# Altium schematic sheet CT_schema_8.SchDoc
size 278 x 170 mm
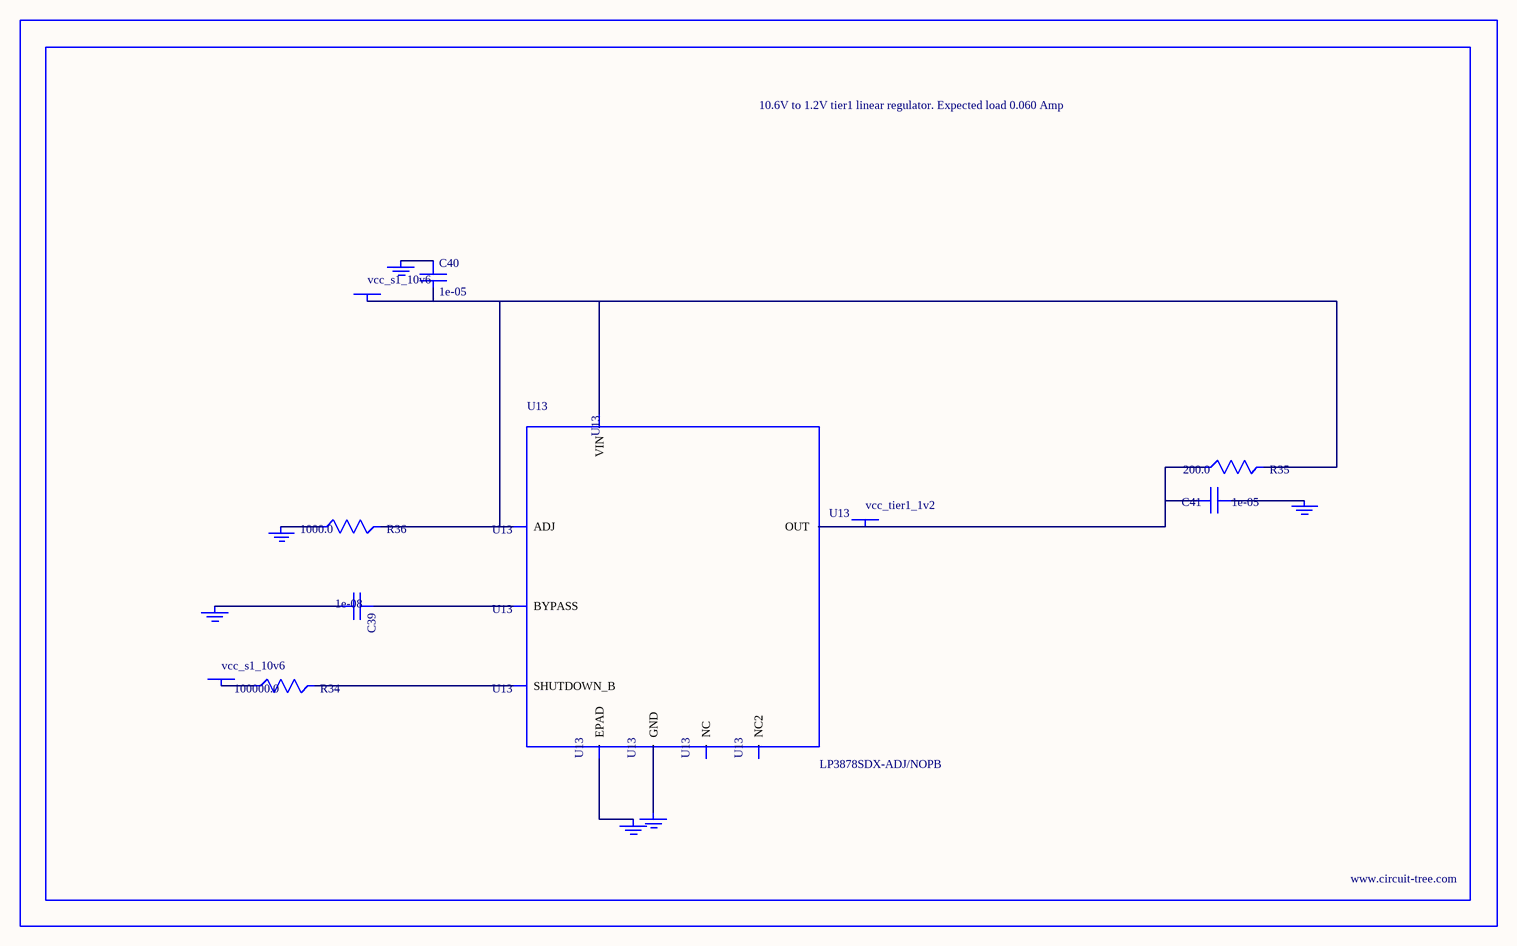
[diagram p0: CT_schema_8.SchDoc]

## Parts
BORDER7  (no value)
C39  1e-08  [C0402]
C40  1e-05  [C1206]
C41  1e-05  [C0805]
GND_INSTANCE_7_0  (no value)
GND_INSTANCE_7_1  (no value)
GND_INSTANCE_7_2  (no value)
GND_INSTANCE_7_3  (no value)
GND_INSTANCE_7_4  (no value)
GND_INSTANCE_7_5  (no value)
POWER_INSTANCE_7_0  vcc_s1_10v6
POWER_INSTANCE_7_1  vcc_s1_10v6
POWER_INSTANCE_7_2  vcc_tier1_1v2
R34  100000.0  [R0603]
R35  200.0  [R0603]
R36  1000.0  [R0603]
U13  LP3878SDX-ADJ/NOPB  [WSON-8]

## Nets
NetC39_1: C39.1 U13.1(BYPASS)
NetC39_2: C39.2 GND_INSTANCE_7_0.0(GND)
NetC40_1: C40.1 GND_INSTANCE_7_1.0(GND)
NetC40_2: C40.2 POWER_INSTANCE_7_0.0(PWR) R35.2 R36.2 U13.4(VIN) U13.6(ADJ)
NetC41_1: C41.1 GND_INSTANCE_7_2.0(GND)
NetC41_2: C41.2 POWER_INSTANCE_7_2.0(PWR) R35.1 U13.5(OUT)
NetGND_INSTANCE_7_3_0: GND_INSTANCE_7_3.0(GND) R36.1
NetGND_INSTANCE_7_4_0: GND_INSTANCE_7_4.0(GND) U13.PAD(EPAD)
NetGND_INSTANCE_7_5_0: GND_INSTANCE_7_5.0(GND) U13.3(GND)
NetPOWER_INSTANCE_7_1_0: POWER_INSTANCE_7_1.0(PWR) R34.1
NetR34_2: R34.2 U13.8(SHUTDOWN_B)

Not connected (* = marked no-connect by the designer): U13 2(NC) 7(NC2)

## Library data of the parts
BORDER7 = BORDER_PAGE7
C39 = C0402C103K3RAC
C40 = C1206C106K3RACTU
C41 = GRM219R60J106ME19D
GND_INSTANCE_7_0-GND_INSTANCE_7_5 = GND
POWER_INSTANCE_7_0-POWER_INSTANCE_7_2 = PWR
R34 = RC0603JR-07100KL
R35 = RC0603JR-07200RL
R36 = RC0603JR-071KL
